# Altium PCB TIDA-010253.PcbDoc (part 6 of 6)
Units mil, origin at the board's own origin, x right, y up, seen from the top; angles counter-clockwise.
Board outline 5525 x 6695 mil, 4 copper layers (Top Layer, Signal Layer 1, Signal Layer 2, Bottom Layer), stack 61.2 mil thick; 522 components, 391 nets, 1722 pads, 1048 vias.
Unrouted connection lines stored in the file: 22.
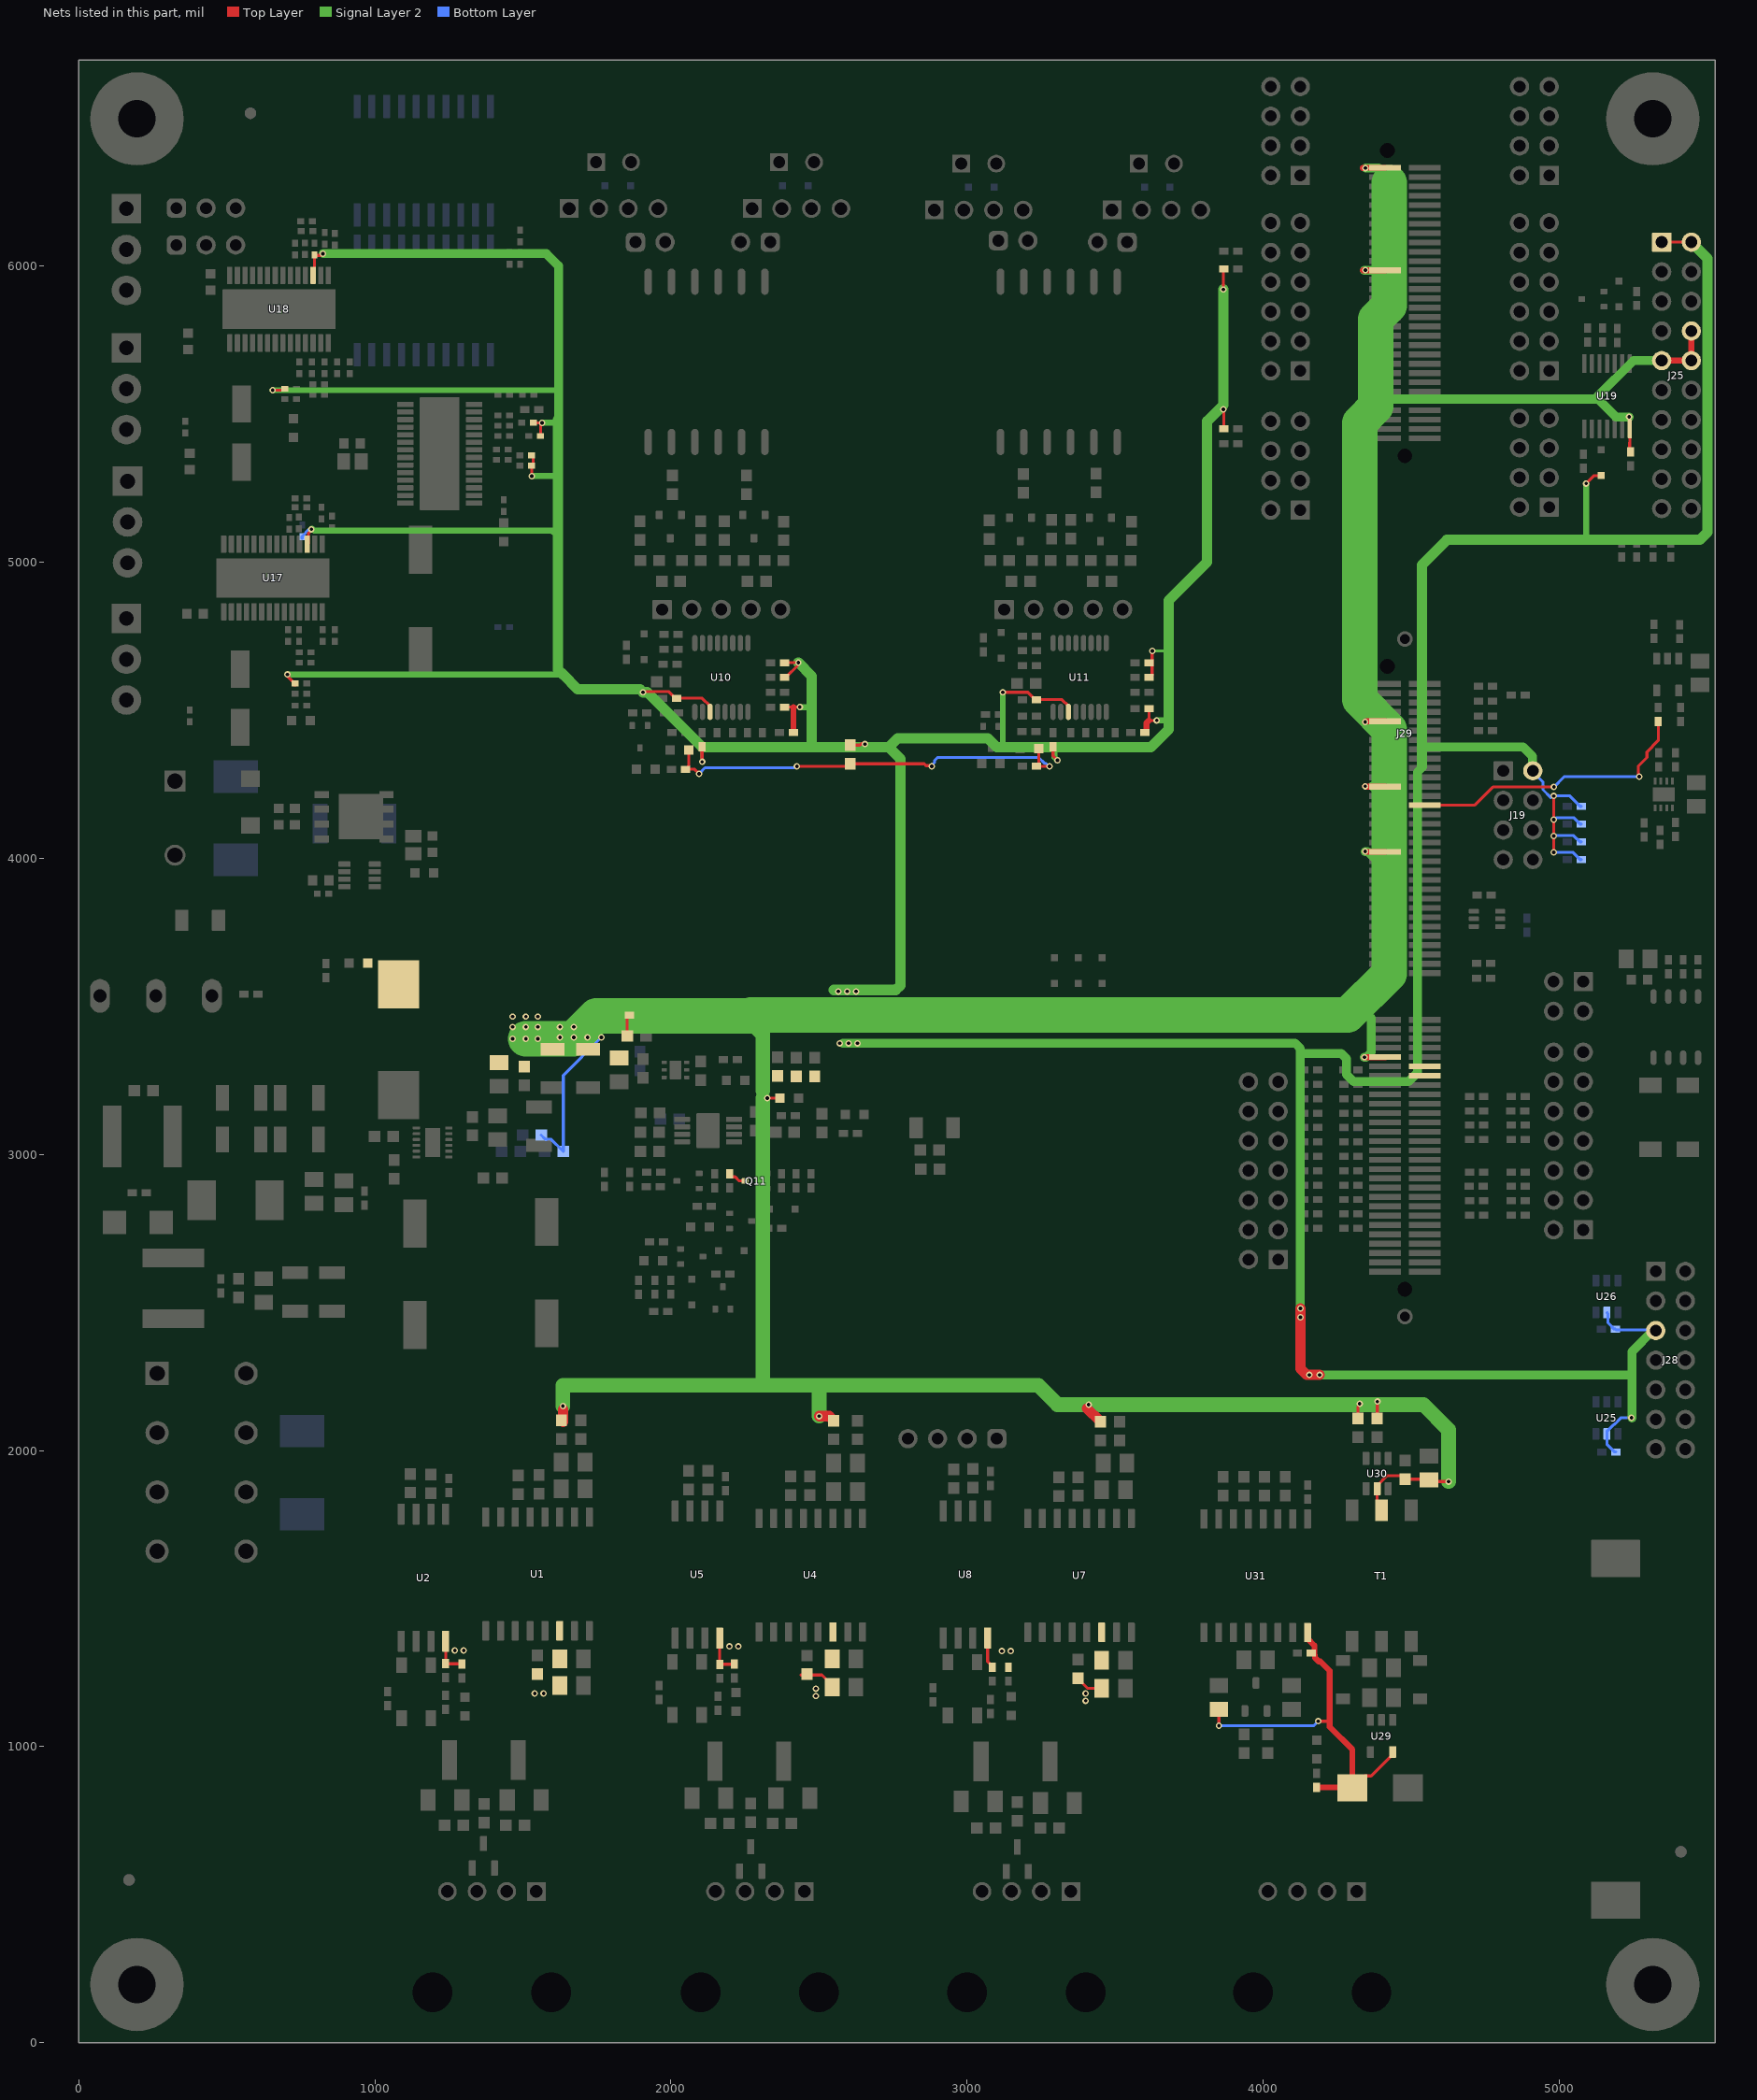
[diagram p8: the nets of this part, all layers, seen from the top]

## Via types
v1: diameter 22, hole 12, Top Layer to Bottom Layer, 944 vias
v2: diameter 19.68, hole 7.87, Top Layer to Bottom Layer, 76 vias
v3: diameter 19.68, hole 7.87, Top Layer to Bottom Layer, tented both sides, 16 vias
v4: diameter 22, hole 12, Top Layer to Bottom Layer, tented both sides, 12 vias

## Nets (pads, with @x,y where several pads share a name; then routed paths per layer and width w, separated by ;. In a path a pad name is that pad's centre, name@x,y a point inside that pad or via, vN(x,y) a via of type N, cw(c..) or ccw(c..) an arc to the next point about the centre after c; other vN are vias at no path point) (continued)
VCC5V: C49.1 C75.1 C113.1 C141.1 CO6.2 CO7.2 CO8.1 CO9.1 CO10.1 D35.2 D38.2 J25.8 J25.9 J25.10 J29.48 J29.84 J29.98 J29.112 J29.158 J29.180 L5.2 R5.1 R17.1 R30.1 R127.1 R133.2 R149.1 R208.1 R212.1 T1.2 U19.14 U30.2 | length 13922.4
  Top Layer w10: R127.1@1852,3400 1852,3463.19 1858.81,3470 R149.1@1859.99,3470 ; v1(2324.99,3190) D35.2@2367,3190 ; R212.1@4319.17,2107.36 4319.17,2148.22 ; R208.1@4384.17,2107.36 4385,2108.19 v1@4385,2155 ; T1.2@4399.17,1798.15 4384.17,1813.15 U30.2@4384.17,1870.87 4384.17,1880.71 4418.46,1915 4467.04,1915 C113.1@4479.17,1902.87 4557.16,1902.87 C141.1@4559.17,1900.87 4565.03,1895 v1(4625,1895) ; C75.1@5236.81,5380.43 5236.81,5402.48 5237.36,5403.03 U19.14@5237.36,5449.53
  Top Layer w20: v1@4335,6330 4335.54,6330 4336.37,6330.83 J29.180@4411.14,6330.83 ; v1@4335.54,5985 4336.17,5984.37 J29.158@4411.14,5984.37 ; v1(4341,3327.68) 4341.32,3327.99 4410.98,3327.99 J29.48@4411.14,3328.15 ; v1(4343.84,4022.68) 4344.38,4022.68 4346,4021.06 J29.84@4411.14,4021.06 ; v1(4343.84,4242.68) 4344.38,4242.68 4345.53,4241.54 J29.98@4411.14,4241.54 ; v1(4343.84,4460) 4344.38,4460 4346.39,4462.01 J29.112@4411.14,4462.01 ; J25.9@5345,5680 J25.10@5445,5680 J25.8@5445,5780
  Top Layer w35: R5.1@1635.83,2095.66 1635.83,2138.5 ; v1(2500,2115.87) 2534.17,2115.87 2546.98,2103.05 2547.97,2103.05 2549.17,2101.85 R17.1@2549.17,2100.87 ; 3405,2141.5 3447.81,2098.68 3448.8,2098.68 3450,2097.48 R30.1@3450,2096.5
  Signal Layer 2 w10: 2269.99,3445 2269.99,3460 ; 2310,3214.99 2324.99,3200 v1(2324.99,3190)
  Signal Layer 2 w30: v1@4340,5985 4385,5985 ; v1(4341,3327.68) 4347.43,3327.68 4365,3345.25 4365,3460 ; v1(4343.84,4022.68) 4352.32,4022.68 4375,4000 ; v1(4343.84,4460) 4375,4460 ; v1(4345,6330) 4390,6330 4420,6300 ; 4367.32,4242.68 4408.51,4201.49 ; 4380,5550 5130,5550 5190,5490 v1(5235,5490) ; 5127.5,5557.5 5250,5680 J25.9@5345,5680
  Signal Layer 2 w35: v1@4322.7,2155 v1(4325.16,2157.46) v1@4327.62,2155
  Signal Layer 2 w50: v1(1635,2150) 1635,2220 2310,2220 ; 2269.99,3445 2310,3404.99 2310,3214.99 ; 2310,3190 2310,2220 ; v1(2500,2115.87) 2500,2210 ; v1@4322.7,2155 v1(3410,2155) 3305,2155 3240,2220 2310,2220 ; v1@4327.62,2155 4385,2155 4540,2155 4625,2070 v1(4625,1895)
  Signal Layer 2 w120: v1(1509.99,3390) 1554.99,3390 1670,3390 1747.5,3467.5 2269.99,3467.5 ; 2269.99,3470 4285,3470 4425,3610 4425,4435 4325,4535 4325,5470 4380,5525 4380,5550 4380,5820 4425,5865 4425,6280
  Bottom Layer w10: C49.1@1561.48,3065 1575.19,3051.3 1594.2,3051.3 1635.5,3010 R133.2@1636.48,3010 1636.48,3266.5 v1(1764.99,3395)
  other v1: 4385,2165 1464.99,3390 1549.99,3390 1624.99,3395 1671.66,3395 1718.32,3395 1464.99,3430 1509.99,3430 1549.99,3430 1624.99,3430 1671.66,3430 1464.99,3465 1509.99,3465 1549.99,3465 4345,5985
VCC5V_485: C114.1 C139.2 R207.1 R216.1 U29.5 U31.16 | length 1347.1
  Top Layer w10: v1(3850,1070.87) R216.1@3850,1125.87 ; R216.1@3850,1135.87 R216.1@3856.5,1135.87 ; C139.2@4162.24,1315.87 C139.2@4166.18,1315.87 ; R207.1@4180,858.31 R207.1@4180,862.24 ; v1(4185,1085.87) 4223.6,1085.87 ; C114.1@4300.66,870.87 C114.1@4300.66,860.87 4340.94,901.14 4363.85,901.14 4436.57,973.86 U29.5@4436.57,981.73
  Top Layer w20: U31.16@4149.17,1384.96 4149.17,1364.29 4172.36,1341.1 4172.36,1310.24 C139.2@4174.17,1308.43 ; C139.2@4174.17,1304.49 4174.17,1300.55 4186.73,1287.99 4192.19,1287.99 4223.6,1256.59 4223.6,1085.87 4223.6,1067.27 4300.66,990.2 C114.1@4300.66,870.87 ; R207.1@4180,862.24 4299.29,862.24 C114.1@4300.66,860.87
  Bottom Layer w10: v1(3850,1070.87) 4170,1070.87 v1(4185,1085.87)
VCC5V_CAN0: C2.2 C4.1 CO2.1 R2.1 R7.2 U1.14 U2.8 | length 131.6
  Top Layer w10: U2.8@1239.17,1356.02 C2.2@1239.17,1280 1292.79,1280 R2.1@1294.17,1278.62
  other v1: 1540,1180 1570,1180 1270,1325 1300,1325
VCC5V_CAN1: C9.2 C11.1 CO4.1 R16.1 R20.2 U4.14 U5.8 | length 265.2
  Top Layer w10: U5.8@2164.17,1366.89 C9.2@2164.17,1278.11 2212.79,1278.11 R16.1@2214.17,1279.49 ; 2439.17,1241.89 2509.64,1241.89 2544.17,1207.37 C11.1@2544.17,1200.87
  other v1: 2489.17,1170.87 2489.17,1195.87 2197.3,1338.29 2227.3,1338.29
VCC5V_CAN2: C16.2 C18.1 CO11.1 R29.1 R33.2 U7.14 U8.8 | length 198.1
  Top Layer w10: U8.8@3069.17,1366.02 3069.17,1287.56 3084.17,1272.56 C16.2@3084.17,1268.62 ; R33.2@3374.17,1230.55 3374.17,1229.57 3406.69,1197.05 C18.1@3454.17,1197.05
  other v1: 3400,1155 3400,1180 3117.3,1322.42 3147.3,1322.42
VDDIO: C25.1 C36.1 C64.1 C65.1 C128.1 C129.1 D24.1 J19.2 J25.1 J25.2 J28.5 R41.2 R42.2 R47.1 R48.1 R49.1 R58.2 R59.2 R64.1 R65.1 R66.1 R71.1 R76.2 R77.2 R78.2 R79.2 R98.2 R100.2 R129.1 R130.1 R131.1 R159.2 R160.2 R199.2 R200.2 R222.2 R223.2 U10.3 U11.3 U17.3 U18.3 U25.5 U26.5 | length 22493.6
  Top Layer w10: v1(655,5580) 681,5580 681.16,5580.16 690.79,5580.16 R100.2@695.63,5585 ; v1@705.38,4613.28 R98.2@728.66,4590 ; U17.3@771.18,5056.5 775.27,5060.58 775.27,5096.72 787.65,5109.1 v1@787.65,5112.35 ; U18.3@791.18,5966.5 791.18,5987.17 796.02,5992.01 C65.1@796.02,6037.32 ; C65.1@805,6035 815.75,6035 821.75,6041 v4(825,6041) ; R76.2@1529.69,5325 1529.84,5324.84 1529.84,5290.16 v1(1530,5290) ; R76.2@1534.69,5325 R77.2@1534.69,5360 ; R79.2@1535,5470 v1(1565,5470) ; R78.2@1559.69,5425 v1@1559.69,5461.44 ; v1@1911.81,4561.81 1992.87,4561.81 2014.68,4540 C25.1@2018.62,4540 2105.25,4540 2131.61,4513.64 U10.3@2131.61,4493.86 ; v1@2105,4335 R42.2@2105,4376.38 ; R49.1@2383.62,4510 2413.62,4510 v1(2435,4510) ; R48.1@2383.62,4610 2387.56,4610 2427.7,4650.14 2427.7,4657.7 v1(2430,4660) R47.1@2383.62,4660 ; R71.1@2605,4381.5 2637.92,4381.5 2642.67,4386.24 v1@2645.92,4386.24 ; v1@3118.3,4560 v1(3120,4560) 3204.68,4560 3229.68,4535 C36.1@3233.62,4535 3320.25,4535 3341.61,4513.64 U11.3@3341.61,4493.86 ; R59.2@3290,4376.38 3290,4345.63 3305,4330.63 v1(3305,4330) ; R66.1@3613.62,4505 3613.62,4464.33 3639.33,4464.33 v1(3640,4465) ; R65.1@3613.62,4610 3617.56,4610 3624.37,4616.81 3624.37,4699.37 v1(3625,4700) ; v4(3865,5920) 3865,5988.62 R199.2@3866.38,5990 ; R200.2@3866.38,5450 v4@3866.38,5515 ; v1(4980,4020) v1(4980,4075) v1(4980,4130) v1(4980,4210) ; v1(5090,5265) 5116.69,5291.69 D24.1@5140,5291.69 ; J28.5@5310.61,2405 J28.5@5325,2405 ; J25.1@5345,6080 J25.2@5445,6080
  Top Layer w20: v1(705,4620) v1@705.38,4619.62 ; R98.2@728.66,4590 R98.2@730.31,4590 ; R41.2@2413.62,4425 2413.62,4510 ; R58.2@3600,4425 3603.94,4425 3605.75,4426.81 3605.75,4456.46 3613.62,4464.33
  Top Layer w35: v1(4125,2480) v1(4125,2450) 4125,2275.5 4145.5,2255 v1(4190,2255)
  Signal Layer 2 w10: v1@2105,4335 2105,4375 ; v1(3625,4700) 3680,4700
  Signal Layer 2 w20: v1(655,5580) 1610,5580 ; v1(705,4620) 1618.53,4620 1635,4620 ; v1@787.65,5112.35 788.19,5112.35 795.17,5105.37 1598.35,5105.37 1603.31,5100.41 ; v1@1535,5290 1615,5290 ; v1(1565,5470) 1615,5470 ; v1(2435,4510) 2465,4510 ; 3120,4380 v1(3120,4560) ; 3290,4365 3295,4360 3295,4340.54 3305,4330.54 v1(3305,4330) ; v1(3640,4465) 3680,4465 ; 5090,5090 v1(5090,5265)
  Signal Layer 2 w30: v4(825,6041) 1579,6041 1620,6000 1620,5470 ; v1@2579.63,3375 v1(2599.99,3375) v1(2629.99,3375) 4107.43,3375 4125,3357.43 4125,3340 ; v1(4125,2450) v1(4125,2480) 4125,3340 ; v1@4160,2255 v1(4190,2255) 5235,2255 5245,2245 ; 4535,4376 4876.43,4376 4908.31,4344.12 4908.31,4301.69 J19.2@4915,4295 ; 4537.5,4307.5 4520,4290 4520,3275 4490,3245 4305,3245 4281.26,3268.74 4281.26,3322.43 4263.69,3340 4125,3340 ; v1@5245,2110 5245,2245 ; J28.5@5325,2405 5315.54,2405 5245,2334.46 5245,2245
  Signal Layer 2 w35: 1618.53,5480 1618.53,4636.47 1635,4620 1685,4570 1895,4570 v1(1905,4560) 1920,4560 2105,4375 2705,4375 2735,4375 ; v1(2430,4660) 2475,4615 2475,4385 ; 2550,3555 2759.5,3555 2775,3570.5 2775,4335 2735,4375 ; v4(3865,5920) 3865,5530 3810,5475 3810,5000 3680,4870 3680,4700 3680,4465 3680,4435 3620,4375 3295,4375 3120,4375 3100,4375 3070,4405 2765,4405 2735,4375 ; 4535,4310 4535,4376 4535,4990 4620,5075 5474.5,5075 5499.98,5100.48 5499.98,6025.02 J25.2@5445,6080
  Bottom Layer w10: C64.1@754.17,5079.49 754.17,5086.14 778.08,5110.05 785.35,5110.05 v1@787.65,5112.35 ; J19.2@4915,4295 4915,4285.85 4944,4256.85 4944,4231.13 4970,4205.13 ; v1(4980,4020) 5044.69,4020 5069.69,3995 R159.2@5073.62,3995 ; v1(4980,4075) 4981.81,4076.81 5046.27,4076.81 5058.08,4065 5059.69,4065 5069.69,4055 R160.2@5073.62,4055 ; v1(4980,4130) 4983.25,4130 4990.06,4136.81 5047.87,4136.81 5069.69,4115 R222.2@5073.62,4115 ; v1(4980,4210) 5034.69,4210 5069.69,4175 R223.2@5073.62,4175 ; U26.5@5160,2465.87 5163.5,2462.36 5163.5,2431.18 5184.68,2410 C129.1@5188.62,2410 5191.12,2407.5 5322.5,2407.5 J28.5@5325,2405 ; C128.1@5190,1995 5186.06,1995 5160,2021.06 U25.5@5160,2055.87 5160,2063.74 5206.26,2110 v1@5240,2110
  other v1: 5243,2110 4155,2255 2570,3375 2565,3550 2594.99,3550 2624.99,3550 2105,4325 2655,4385 785.65,5110.35
  other v4: 3865,5515
VDDIO_LED: D11.2 D16.2 R52.2 R69.2 R71.2 | length 1443.4
  Top Layer w10: R52.2@2048.62,4300 2080,4300 v1(2095,4285) ; R52.2@2053.19,4305 2060,4311.81 D11.2@2060,4365 ; v1(2425,4310) 2596.5,4310 R71.2@2605,4318.5 2855,4318.5 2861.21,4312.3 2877.7,4312.3 v1(2880,4310) ; R69.2@3233.62,4310 R69.2@3234.69,4310 ; D16.2@3241.5,4370 3241.5,4316.81 R69.2@3234.69,4310 ; v1(3278,4310) R69.2@3234.69,4310
  Bottom Layer w10: v1(2095,4285) 2115,4305 v1@2416.75,4305 ; v1(2880,4310) 2880,4313.25 2890,4323.25 2890,4330 2900,4340 3241.75,4340 3261.97,4319.79 3264.97,4319.79 3274.75,4310 v1(3278,4310)
VREFHI: J29.45
VREFLO: J29.43
WAKE_C: Q11.3 R143.1 | length 64.2
  Top Layer w10: R143.1@2197.59,2933.62 2197.59,2930.44 2204.4,2923.63 2216.37,2923.63 2229.52,2910.48 2249.71,2910.48 Q11.3@2250.19,2910
WTD_WI: J29.93 R154.2 | length 974.9
  Top Layer w10: J29.93@4545,4178.54 4545.73,4179.27 4714.27,4179.27 4775,4240 v1@4980,4240 ; v1@5266,4275 5266,4311 5295,4340 5295,4358.5 5333.62,4397.13 R154.2@5333.62,4461.38
  Bottom Layer w10: v1(4981,4240) 5015,4274 5015,4275 v1@5266,4275
  other v1: 5269,4275
pads on no net: FID1.1 FID2.1 FID3.1 FID4.1 FID5.1 FID6.1 H1.1 H2.1 H3.1 H4.1 J1.1 J1.MH1 J1.MH2 J2.1 J2.MH1 J2.MH2 J4.1 J4.2 J8.3 J8.4 J9.1 J9.2 J13.3 J13.4 J20.1 J20.3 J25.4 J25.6 J25.12 J25.14 J25.16 J28.6 J29.41 J29.44 J29.56 J29.66 J29.68 J29.70 J29.113 J29.114 J29.115 J29.116 J29.117 J29.118 J29.119 J29.136 J29.171 J29.172 J29.173 J29.174 J29.175 J29.176 J29.177 J29.178 J29.181 J29.182 J29.183 J29.184 J29.185 J29.186 J30.1 J30.MH1 J30.MH2 J31.1 J31.MH1 J31.MH2 LBL1.0 T2.8 T2.11 T3.8 T3.11 U13.2 U13.19 U13.24 U13.29@1218.86,5365.43 U14.4 U14.7 U15.10 U15.11 U16.10 U16.11 U19.3 U19.11 U22.5 U22.7@2014.99,3267.28 U22.7@2014.99,3302.72 U23.6 U23.9@2124.99,3080 U29.4 U31.7 U31.10 U31.11 U31.14 Y1.2 Y1.3

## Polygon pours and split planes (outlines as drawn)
GND on Signal Layer 1 "GND_L02_P051" (solid, remove dead copper, pour order 51): 25,6715 25,0 5530,0 5530,6695 5520,6705
PGND on Signal Layer 1 "PGND_L02_P049" (solid, remove dead copper, pour order 49): 0,6695 2020,6695 2030,6705 2935,6705 2935,5 2930,0 0,0
GND2 on Signal Layer 1 "GND2_L02_P066" (solid, remove dead copper, pour order 66): 3790,1385 4560,1385 4560,0 3790,0
GND4 on Signal Layer 1 "GND4_L02_P060" (solid, remove dead copper, pour order 60): 2865,1385 3578.5,1385 3578.5,7.48 2865,7.48
GND1 on Signal Layer 1 "GND1_L02_P057" (solid, remove dead copper, pour order 57): 1940,1380 2653.99,1380 2653.99,0 1940,0
GND0 on Signal Layer 1 "GND0_L02_P054" (solid, remove dead copper, pour order 54): 1018.15,1385 1750,1385 1750,0 1028.15,0 1028.15,500 1018.15,500
GND on Bottom Layer "GND_L04_P069" (solid, remove dead copper, pour order 69): 25,6715 25,0 5530,0 5530,6695 5520,6705
PGND on Bottom Layer "PGND_L04_P048" (solid, remove dead copper, pour order 48): 0,6695 2020,6695 2030,6705 2935,6705 2935,5 2930,0 0,0
GND0 on Bottom Layer "GND0_L04_P056" (solid, remove dead copper, pour order 56): 1018.15,1385 1750,1385 1750,0 1028.15,0 1028.15,500 1018.15,500
GND1 on Bottom Layer "GND1_L04_P059" (solid, remove dead copper, pour order 59): 1940,1380 2653.99,1380 2653.99,0 1940,0
GND2 on Bottom Layer "GND2_L04_P068" (solid, remove dead copper, pour order 68): 3790,1385 4560,1385 4560,0 3790,0
GND4 on Bottom Layer "GND4_L04_P062" (solid, remove dead copper, pour order 62): 2865,1385 3578.5,1385 3578.5,7.48 2865,7.48
GND on Top Layer "GND_L01_P065" (solid, remove dead copper, pour order 65): 25,6715 25,0 5530,0 5530,6695 5520,6705
PGND on Top Layer "PGND_L01_P021" (solid, remove dead copper, pour order 21): 0,6695 2020,6695 2030,6705 2935,6705 2935,5 2930,0 0,0
GND1 on Top Layer "GND1_L01_P023" (solid, remove dead copper, pour order 23): 1940,1380 2653.99,1380 2653.99,0 1940,0
GND0 on Top Layer "GND0_L01_P022" (solid, remove dead copper, pour order 22): 1018.15,1385 1750,1385 1750,0 1028.15,0 1028.15,500 1018.15,500
GND2 on Top Layer "GND2_L01_P064" (solid, remove dead copper, pour order 64): 3790,1385 4560,1385 4560,0 3790,0
GND4 on Top Layer "GND4_L01_P038" (solid, remove dead copper, pour order 38): 2865,1385 3578.5,1385 3578.5,7.48 2865,7.48
GND on Signal Layer 2 "GND_L03_P052" (solid, remove dead copper, pour order 52): 25,6715 25,0 5530,0 5530,6695 5520,6705
PGND on Signal Layer 2 "PGND_L03_P045" (solid, remove dead copper, pour order 45): 0,6695 2020,6695 2030,6705 2935,6705 2935,5 2930,0 0,0
GND0 on Signal Layer 2 "GND0_L03_P053" (solid, remove dead copper, pour order 53): 1018.15,1385 1750,1385 1750,0 1028.15,0 1028.15,500 1018.15,500
GND2 on Signal Layer 2 "GND2_L03_P067" (solid, remove dead copper, pour order 67): 3790,1385 4560,1385 4560,0 3790,0
GND4 on Signal Layer 2 "GND4_L03_P061" (solid, remove dead copper, pour order 61): 2865,1385 3578.5,1385 3578.5,7.48 2865,7.48
GND1 on Signal Layer 2 "GND1_L03_P055" (solid, remove dead copper, pour order 55): 1940,1380 2653.99,1380 2653.99,0 1940,0

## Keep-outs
Keep-Out Layer:
  text ".Layer_Name" at 577,-858.49 h60

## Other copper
Top Layer:
  region net HS_OUT2: 1010,5305 1010,5225 1065,5225 1065,5240 1135,5240 1135,5280 1070,5280 1070,5300 1065,5305
  region net LS_OUT4: 580,5945 580,6110 640,6110 645,6105 645,5945
  region net LS_OUT3: 580,5765 580,5705 575,5700 605,5670 645,5710 645,5765
  region net HS_OUT4: 655,5770 725,5770 720,5765 720,5605 715,5600 655,5600
  region net HS_OUT4: 655,5940 655,6105 710,6105 715,6100 715,5940
  region net LS_OUT2: 560,5030 560,5090 430,5220 110,5220 110,5325 180,5325 185,5320 190,5325 440,5325 625,5140 625,5035
  region net HS_OUT1: 1075,5215 1075,5235 1130,5235 1130,5165 1130,5160 1120,5160 1010,5160 1010,5215
  region net HS_OUT1: 985,521 985,461 1137.5,461 1137.5,521
  region net VCC5V: 979.99,3480 1009.99,3450 1119.99,3450 1239.99,3330 1289.99,3280 1559.99,3280 1584.99,3295 1874.99,3295 1874.99,3480 1844.99,3480 1844.99,3425 1839.99,3420 1794.99,3420 1769.99,3445 1619.99,3445 1609.99,3455 1609.99,3490 1454.99,3645 979.99,3645
  region net PGND: 2084.99,3120 2086.6,3118.39 2249.63,3118.39 2259.55,3128.31 2262.86,3125 2324.99,3125 2324.99,3160 2279.99,3205 2204.99,3205 2204.99,3265 2199.99,3270 2034.99,3270 2034.99,3335 2059.99,3335 2064.99,3340 2064.99,3390 1969.99,3390 1969.99,3340 1979.99,3340 1994.99,3325 1994.99,3270 1881.49,3270 1881.49,3260 1412.49,3260 1404.99,3260 1369.99,3225 1164.99,3225 1164.99,2980 1139.99,2955 1029.99,2955 904.99,3080 904.99,3185 904.99,3455 857.85,3455 310,3455 245,3390 245,2955 504.99,2955 504.99,3260 760,3260 760,2865 1394.99,2865 1394.99,2985 1279.99,2985 1279.99,2970 1244.99,2970 1224.99,2990 1224.99,3106.5 1328.49,3106.5 1328.49,3110 1914.99,3110 1914.99,3185 2084.99,3185
  region net GND: 3509.17,1982.05 3509.17,1822.05 3489.17,1802.05 3489.17,1737.05 3514.17,1737.05 3519.17,1742.05 3519.17,1792.05 3605,1877.88 3605,1982.05
  region net NetC17_1: 3439.17,1732.05 3459.17,1732.05 3469.17,1742.05 3469.17,1807.05 3489.17,1827.05 3489.17,1982.05 3519.17,2012.05 3534.17,2012.05 3534.17,2047.05 3539.17,2052.05 3429.17,2052.05 3429.17,1742.05
  region net GND: 3194.17,1737.05 3314.17,1737.05 3314.17,1792.05 3279.17,1827.05 3279.17,1882.05 3279.17,1887.05 3404.17,1887.05 3414.17,1897.05 3414.17,1972.05 3219.17,1972.05 3194.17,1947.05
  region net VCC5V_CAN2: 3070,1385 3070,1260 3075,1255 3165,1255 3165,1385
  region net GND4: 3539.9,1354.27 3504.9,1319.27 3499.9,1319.27 3499.9,1169.27 3509.9,1159.27 3569.9,1159.27 3569.9,1351.32 3566.94,1354.27
  region net VCC5V_CAN2: 3350,1260 3350,1160 3370,1140 3475,1140 3480,1145 3479.17,1145.83 3479.17,1250.83 3470,1260
  region net GND4: 3186.67,1422.05 3306.67,1422.05 3311.67,1417.05 3361.67,1417.05 3361.67,1357.05 3331.67,1327.05 3331.67,1157.05 3356.67,1132.05 3486.67,1132.05 3486.67,1162.05 3505.42,1180.8 3524.17,1162.05 3566.67,1162.05 3566.67,1070.91 3547.8,1052.05 3181.67,1052.05
  region net VCC5V_CAN2: 3439.9,1354.27 3424.9,1339.27 3424.9,1159.27 3474.9,1159.27 3474.9,1164.27 3474.9,1344.27 3464.9,1354.27
  region net GND4: 3127.13,1126.38 3120,1119.25 3120,1045 3200,1045 3240,1085 3240,1125
  region net NetC10_1: 2534.17,1735.87 2554.17,1735.87 2564.17,1745.87 2564.17,1810.87 2584.17,1830.87 2584.17,1985.87 2614.17,2015.87 2629.17,2015.87 2629.17,2050.87 2634.17,2055.87 2524.17,2055.87 2524.17,1745.87
  region net VCC5V_CAN1: 2150,1400.87 2150,1275.87 2155,1270.87 2245,1270.87 2245,1400.87
  region net GND: 2289.17,1740.87 2409.17,1740.87 2409.17,1795.87 2374.17,1830.87 2374.17,1885.87 2374.17,1890.87 2499.17,1890.87 2509.17,1900.87 2509.17,1975.87 2314.17,1975.87 2289.17,1950.87
  region net GND1: 2207.13,1132.24 2200,1125.12 2200,1050.87 2280,1050.87 2320,1090.87 2320,1130.87
  region net VCC5V_CAN1: 2435,1275.87 2435,1175.87 2455,1155.87 2560,1155.87 2565,1160.87 2564.17,1161.7 2564.17,1266.7 2555,1275.87
  region net VCC5V_CAN1: 2534.9,1358.09 2519.9,1343.09 2519.9,1163.09 2569.9,1163.09 2569.9,1168.09 2569.9,1348.09 2559.9,1358.09
  region net GND: 2604.17,1985.87 2604.17,1825.87 2584.17,1805.87 2584.17,1740.87 2609.17,1740.87 2614.17,1745.87 2614.17,1795.87 2695,1876.7 2695,1985.87
  region net GND1: 2276.67,1055.87 2642.8,1055.87 2661.67,1074.73 2661.67,1163.09 2664.9,1163.09 2664.9,1348.09 2654.9,1358.09 2634.9,1358.09 2599.9,1323.09 2594.9,1323.09 2594.9,1163.99 2581.67,1155.55 2581.67,1135.87 2451.67,1135.87 2426.67,1160.87 2426.67,1330.87 2456.67,1360.87 2456.67,1420.87 2406.67,1420.87 2401.67,1425.87 2281.67,1425.87
  region net NetC3_1: 1605,1995 1605,2060 1715,2060 1710,2055 1710,2020 1695,2020 1665,1990
  region net NetC3_1: 1615,1745 1605,1755 1605,2000 1660,2000 1665,1995 1665,1840 1645,1820 1645,1755 1635,1745
  region net VCC5V_CAN0: 1520,1265 1520,1165 1540,1145 1645,1145 1650,1150 1649.17,1150.83 1649.17,1255.83 1640,1265
  region net VCC5V_CAN0: 1614.17,1360 1599.17,1345 1599.17,1165 1649.17,1165 1649.17,1170 1649.17,1350 1639.17,1360
  region net GND: 1679.17,1989.17 1679.17,1829.17 1659.17,1809.17 1659.17,1744.17 1684.17,1744.17 1689.17,1749.17 1689.17,1799.17 1770,1880 1770,1989.17
  region net GND: 1364.17,1745 1484.17,1745 1484.17,1800 1449.17,1835 1449.17,1890 1449.17,1895 1574.17,1895 1584.17,1905 1584.17,1980 1389.17,1980 1364.17,1955
  region net GND0: 1364.17,1425 1484.17,1425 1489.17,1420 1539.17,1420 1539.17,1360 1509.17,1330 1509.17,1160 1534.17,1135 1664.17,1135 1664.17,1165 1674.17,1175 1684.17,1165 1744.17,1165 1744.17,1073.86 1725.3,1055 1359.17,1055
  region net GND0: 1714.17,1360 1679.17,1325 1674.17,1325 1674.17,1175 1684.17,1165 1744.17,1165 1744.17,1350 1734.17,1360
  region net VBATF: 1566.16,2695 1629.99,2690 1629.99,2955 1629.99,2990 1884.99,2990 1884.99,3020 1859.99,3045 1604.99,3045 1554.99,3095 1274.99,3095 1234.99,3095 1234.99,3050 1239.99,3045 1279.99,3045 1304.99,3020 1469.99,3020 1469.99,2845 730,2845 705.43,2869.57 705.43,3094.57 704.99,3165 704.99,3240 545,3240 545,2770 620,2695
  region net VBATP: 215.01,2570 900,2570 900,2680 585,2680 495,2770 495,2945 220,2945 215.01,2934.99
  region net PGND: 215,2020 570,2020 570,2115 570,2365 455,2480 215,2480
  region net VBATI: 575,1615 0,1615 0,3390 200,3390 200,1970 575,1970
  region net VCC3V3: 2194.99,3395 2289.99,3395 2289.99,3340 2194.99,3340
  region net VCC3V3: 2279.99,3310 2284.99,3305 2509.99,3305 2509.99,3350 2509.99,3395 2279.99,3395
  region net BQ_12V: 2184.99,3050 2244.99,3050 2249.99,3045 2394.99,3045 2404.99,3055 2404.99,3095 2509.99,3095 2514.99,3090 2514.99,3000 2214.99,3000 2184.99,3030
  region net VCC3V3: 2154.99,3305 2149.99,3310 2149.99,3395 2194.99,3395 2194.99,3305
  region net VDDIO: 2334.99,3290 2334.99,3240 2359.99,3215 2584.99,3215 2599.99,3230 2599.99,3295 2339.99,3295
  region net VDDIO: 2534.99,3295 2534.99,3570 2659.99,3570 2659.99,3215 2539.99,3215
  region net PGND: 1279.99,2985 1259.99,2970 1279.99,2970
  region net NetCBoot1_1: 1028.99,3280 1040,3248.54 1040,3045 1129.99,3045 1149.99,3045 1149.99,3280
  region net PGND: 2084.99,3035 2084.99,3025 2069.99,3010 2069.99,3000 2179.99,3000 2179.99,3010 2164.99,3025 2164.99,3035
  region net PGND: 389.99,2445 484.99,2350 1769.99,2350 1769.99,2465.95 1769.99,2545 954.99,2545 220,2545 220,2445
  region net VCC5V_CAN0: 1225,1390 1225,1265 1230,1260 1320,1260 1320,1390
  region net GND0: 1297.13,1121.38 1290,1114.25 1290,1040 1370,1040 1410,1080 1410,1120
  region net 24V: 1055,4065 1072.5,4082.5 1325,4082.5 1325,4682.5 1385,4742.5 1385,5120 1190,5120 1190,4990 1265,4915 1265,4747.5 1225,4707.5 1225,4267.5 1200,4242.5 875,4242.5 875,4082.5 892.5,4065
  region net PGND: 1365,5635 1565,5635 1585,5615 1585,5605 1395,5605 1375,5585
  region net PGND: 1160,5175 1160,5150 1155,5145 1010,5145 1010,5130 1395,5130 1395,5155 1375,5175
  region net PGND: 1155,5525 1155,5565 1065,5565 1050,5580 1050,5605 1080,5635 1365,5635 1375,5625 1375,5585 1360,5570 1305,5570 1290,5555 1290,5525
  region net PGND: 470,5110 465,5105 465,4795 545,4795 550,4800 550,5085 545,5085 515,5115 465,5115
  region net PGND: 405,4860 405,4810 415,4800 550,4800 550,4860 545,4865 410,4865
  region net PGND: 467.09,5019.49 539.49,5019.49 550,5030 550,5085 545,5085 515,5115 465,5115
  region net 24V_CONN: 610,4055 775,4055 785,4065 785,4095 610,4095
  region net 24V_CONN: 610,4080 645,4080 660,4095 850,4095 850,4120 855,4130 855,4135 855,4230 785,4230 780,4230 770,4225 770,4140 495,4140 450,4095 450,3715 610,3715 610,3880
  region net PGND: 500,5995 570,5995 570,5715 565,5710 500,5710
  region net PGND: 280,4470 650,4470 650,4390 685,4390 700,4405 830,4405 850,4385 850,4270 780,4270 750,4240 750,4155 645,4155 625,4175 280,4175
  region net PGND: 1015,4770 1015,4560 1185,4560 1210,4585 1210,4770
  region net GND: 5285,4285 5285,4205 5300,4190 5410,4190 5425,4175 5425,4060 5495,4060 5495,4200 5445,4200 5405,4240 5335,4240 5330,4240 5330,4270 5310,4290 5305,4305 5285,4305
  region net GND2: 4390,1015.87 4450,1015.87 4460,1005.87 4460,915.87 4445,900.87 4445,820.87 4550,820.87 4550,1050.87 4425,1050.87 4410,1065.87 4410,1098.37 4392.5,1098.37 4390,1095.87
  region net GND2: 4380,1395.87 4335,1350.87 4335,1265.87 4325,1255.87 4270,1245.87 4270,1197.79 4335,1182.79 4335,1135.87 4370,1135.87 4390,1115.87 4390,1075.87 4405,1075.87 4410,1070.87 4410,1125.87 4395,1140.87 4399.17,1145.03 4399.17,1395.03 4400,1395.87
  region net PGND: 265,5420 265,5340 470,5340 535,5275 905,5275 920,5290 920,5445 270,5445
  region net HS_OUT4: 1135,5545 1135,5495 1065,5495 985,5495 985,5545
  region net HS_OUT1: 680,4780 680,4635 655,4610 555,4610 540,4700 570,4725 640,4780
  region net LS_OUT1: 625,4855 560,4855 560,4795 530,4765 530,4714.47 625,4784.47
  region net HS_OUT1: 705,4855 705,4800 695,4800 680,4785 680,4780 660,4780 650,4780 635,4770 635,4800 635,4855
  region net HS_OUT1: 635,5195 635,5035 690.19,5035 700,5085 690,5095 690,5195
  region net LS_OUT1: 531.54,4715 220,4715 175,4760 110,4760 110,4860 329.88,4860 399.88,4790 560.38,4790
  region net HS_OUT1: 535,4580 445,4490 120,4490 120,4545 135,4560 140,4555 420,4555 515,4650 515,4686.5 523.5,4695
  region net 24V: 930,5320 930,4955 1070,4955 1005,5074.74 1005,5320
  region net 24V: 975.29,5120 1200,5120 1210,5110 1210,4955 980,4955
  region net NetF1_1: 195,4045 80,3930 80,3715 375,3715 375,4005 375,4045
  region net HS_OUT3: 1135,5485 1135,5445 1065,5445 1065,5435 975,5435 975,5485
  region net 24V: 1132.68,5316.02 1067.68,5316.02 935,5316.02 935,5426.02 1062.68,5426.02 1082.68,5406.02 1132.68,5406.02
  text ".Layer_Name" at 577,-858.49 h60
Signal Layer 2:
  region net VCC5V: 1449.99,3475 1459.99,3485 1599.99,3485 1639.99,3445 1779.99,3445 1779.99,3345 1764.99,3330 1484.99,3330 1449.99,3365
Bottom Layer:
  region net 24V_CONN: 665,4080 675,4090 675,4120 810,4120 810,4055 665,4055
  region net VCC5V_CAN2: 3085,1385 3080,1380 3080,1150 3440,1150 3450,1150 3450,1180 3450,1240 3200,1240 3170,1270 3170,1385
  region net VCC5V_CAN1: 2165,1400.87 2160,1395.87 2160,1165.87 2520,1165.87 2530,1165.87 2530,1195.87 2530,1255.87 2280,1255.87 2250,1285.87 2250,1400.87
  region net PGND: 217.91,2340.86 222.91,2345.86 835,2345.86 835,2010.86 207.91,2010.86
  region net VBATI: 225,1955 230,1960 830,1960 830,1625 215,1625
  region net VCC5V_CAN0: 1230,1390 1225,1385 1225,1155 1585,1155 1595,1155 1595,1185 1595,1245 1345,1245 1315,1275 1315,1390
  region net LS_OUT_COM: 965,6145 975,6145 1050,6070 1380,6070 1310,6140 1310,6205 1295,6220 935,6220 920,6205 920,6175
  region net 24V: 900,4210 900,4070 1065,4070 1070,4075 1070,4205 1065,4210
  region net PGND: 460,4330 665,4330 735,4400 825,4400 825,4310 825,4300 810,4275 740,4275 690,4225 460,4225
  region net 24V_CONN: 455,4050 455,3850 600,3850 605,3860 605,3875 605,4055
  region net LS_OUT_COM: 930,6190 910,6190 875,6225 875,6320 820,6320 820,6195 870,6145 965,6145
  region net HS_OUT4: 985,5550 1065,5550 1065,5495 975,5495 975,5550
  region net HS_OUT1: 635,5200 635,5105 645,5095 695,5095 695,5200
  text ".Layer_Name" at 577,-858.49 h60
Multi-Layer:
  pour cut-out: 745,1735.87 4400,1735.87 4400,1710 4450,1660 4455,1665 4852.75,1665 4870,1647.74 4870,1540 4845,1565 4845,1645 4400,1645 4375,1670 4375,1710 745,1710
  pour cut-out: 1485,3705 1505,3705 1505,3675 1600,3580 2830,3580 2885,3525 2885,2475 2735,2325 840,2325 840,1805 600,1565 0,1565 0,1600 4.19,1604.19 599.19,1604.19 805,1810 805,2355 2735,2355 2870,2490 2870,3520 2825,3565 1595,3565 1485,3675
  pour cut-out: 1330,4805 1330,4850 1510,5030 1510,5740 1510,6695 1495,6695 1495,5041.25 1315,4861.25 1315,4790
  pour cut-out: 3655.65,4905 3655.65,5920 3965.65,6230 3965.65,6697.28 1510.65,6697.28 1510.65,5950 1800.65,5660 1784.35,4905
  pour cut-out: 4830,1645 4830,0 4870,0 4870,1647.74
  pour cut-out: 1315,3875 1485,3705 1505,3705 1420,3790 1385,3825 1330,3880 1330,4805 1315,4790
  pour cut-out: 5295,3355 5395,3355 5395,3305 5465,3235 5480,3235 5480,2950 5475,2945 5390,2945 5390,2955 5475,2955 5475,3230 5460,3230 5385,3305 5385,3350 5300,3350 5295,3345
  pour cut-out: 5300,3350 5295,3355 5295,3300 5255,3260 5255,2945 5390,2945 5390,2955 5275,2955 5260,2970 5260,3255 5300,3295

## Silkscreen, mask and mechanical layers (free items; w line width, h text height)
Top Overlay:
  lines w10: 470,5225 670,5225 690,5205 ; 755,4640 820,4640 1005,4640 1020,4625 1020,4275 1005,4260 845,4260 835,4270 835,4640 ; 895,5570 915,5550 930,5550 945,5565 945,5570 ; 935,5785 935,5580 945,5570 ; 940,5775 1185,5775 1190,5770 1190,5580 1180,5570 945,5570 ; 1010,6510 1085,6510 ; 1010,6565 1095,6565 1105,6555 1105,6510 ; 1095,6500 1105,6510 ; 1130,6565 1210,6565 ; 1210,6510 1105,6510 ; 1714.99,3695 1714.99,3550 1754.99,3510 2444.99,3510 2464.99,3530 2464.99,3695 ; 1715,3700 1765,3750 2415,3750 2465,3700 ; 1724.99,3480 1749.99,3505 1784.99,3505 ; 1894.99,2475 1894.99,2420 1959.99,2355 ; 1960,2210 1980,2190 2305,2190 2305,2430 2294.99,2440 1964.99,2440 1959.99,2435 ; 1960,2210.87 1960,2435.87 ; 2395,5245 2430,5245 ; 2415,4915 3005,4915 3005,5100 ; 2415,5105 3005,5105 ; 2415,5290 2995,5290 ; 2430,5105 2430,5290 ; 2439.99,2790 2469.99,2760 2509.99,2760 ; 2529.99,2670 2519.99,2680 2519.99,2890 2539.99,2910 ; 2540,2670 3040,2670 3070,2700 3070,2910 2550,2910 ; 2715,5255 2715,5290 ; 2720,5070 2720,5105 ; 3010,4950 3045,4950 ; 5125,6025 5125,5970 5130,5965 ; 290,5070 290,5280 435,5280 465,5250 465,5095 440,5070 290,5070 ; 575,6215 575,6370 590,6385 795,6385 810,6370 810,6195 595,6195 575,6215 ; 1585,4285 1585,4800 1790,4800 1805,4785 1805,4270 1795,4280 1590,4280 1585,4285 ; 2780,4365 2780,4780 2800,4800 2985,4800 2985,4340 2805,4340 2780,4365 ; 2790,3275 2790,3525 3075,3525 3130,3470 3130,3275 2790,3275 ; 5060,6050 5060,6305 5090,6335 5230,6335 5240,6325 5240,6050 5220,6030 5080,6030 5060,6050
  text "LSD_4" at 1240,6545.83 h35
  text "GND" at 890,6535 h35
  text "LSD_C" at 825,6480.83 h35
  text "PCHG" at 1245,6480 h35
  text "UIR" at 5295,6225 h80
  text "X=4,3,2,1 / LSD_X / LSD_C / HSD_X" at 970,6070 h50
  text "BQ0" at 2460,5555 h80
  text "BQ1" at 2780,5555 h80
  text "H->L" at 2605,5455 h60
  text "PN NP" at 2585,5365 h60
  text "GND/VIO" at 5005,4280.02 h60
  text "DVDD" at 3005,4245 h30
  text "FLT" at 3165,4245 h30
  text "DVDD" at 1820,4225 h30
  text "FLT" at 1980,4225 h30
  text "IC_2/1_IO" at 5005,4149.99 h60
  text "IC2_D/CL" at 5005,4075 h30
  text "IC1_D/CL" at 5005,3980 h30
  text "24V" at 1224,3879 h25
  text "24V_2" at 75,3763.33 h50
  text "12V" at 2695,3615 h50
  text "5VPG" at 2799,3479 h25
  text "5V" at 2859,3444 h25
  text "3.3V" at 2315,3435 h50
  text "33V" at 2894,3409 h25
  text "5V" at 1320,3390 h50
  text "BQ0/BQ1/IG / wake" at 3160,3370 h50
  text "12PG" at 2934,3369 h25
  text "12V" at 3044,3344 h25
  text "BAT" at 2899,3329 h25
  text "OFF" at 360,3310 h50
  text "ON" at 50,3305 h50
  text "K15" at 2844,3289 h25
  text "VDDIO" at 2545,3235 h50
  text "MCU_WK" at 2515,2933.33 h50
  text "5V" at 1590,2240 h50
  text "DE" at 3920,2205 h50 r270
  text "RE" at 3990,2200 h50 r270
  text "TX" at 1165,2195 h50 r270
  text "RX" at 1085,2190 h50 r270
  text "PGND" at 680,2155 h50
  text "D" at 3845,2155 h50 r270
  text "R" at 4065,2150 h50 r270
  text "3.3V" at 1310,2100 h50 r270
  text "5V" at 4675,1860 h50
  text "Debug" at 5065,1816.66 h80
  text "24V_1" at 670,1773.33 h50
  text "L" at 1470,580 h50
  text "A" at 4100,580 h50
  text "B" at 4190,580 h50
  text "H" at 1235,570 h50
  text "CAN1" at 1895,135 h80 r90
  text "RS485" at 3720.15,131.06 h80 r90
  text "CAN0" at 950,115 h80 r90
  text "CAN2" at 2775.15,111.06 h80 r90
  text ".Layer_Name" at 577,-858.49 h60
Bottom Overlay:
  text "GND" at 4194,6594 h20
  text "GND" at 4299,6594 h20
  text "GND" at 4494,6464 h20
  text "GND" at 4663.33,6463.66 h20
  text "AMUR2_TX" at 4664,6427.33 h20
  text "AMUR0_TX" at 4193.53,6387.8 h20
  text "AMUR2_RX" at 4493.53,6387.8 h20
  text "AMUR0_RX" at 4658.53,6387.8 h20
  text "AMUR1_RX" at 4494,6352.33 h20
  text "ＶＤＤＩＯ" at 5099,6254 h20
  text "VDDIO" at 5204,6254 h20
  text "OC1" at 5097.96,6213.83 h20
  text "AMUR1_TX" at 3968.53,6212.8 h20
  text "STEAP1" at 4137.45,6210.15 h20
  text "GND" at 4839,6184 h20
  text "GND" at 4944,6184 h20
  text "OC2" at 5097.96,6173.83 h20
  text "nFLT" at 5097.96,6138.83 h20
  text "VCC5V" at 5204,6138.83 h20
  text "GND" at 4184,6129 h20
  text "GND" at 4289,6129 h20
  text "VCC5V" at 5097.96,6103.83 h20
  text "VCC5V" at 5204,6104 h20
  text "MOSI" at 5100.35,6068.78 h20
  text "MISO" at 5099,6034 h20
  text "CS" at 5099,5999 h20
  text "CLK" at 5099,5964 h20
  text "UIREN" at 5204,5964 h20
  text "GND" at 5099,5924 h20
  text "GND" at 5204,5924 h20
  text "GND" at 5018.77,5470.74 h20
  text "GND" at 3929,5464 h20
  text "STRAP2" at 3869,5374 h20
  text "LSD_FT1" at 4794,5092.33 h20
  text "FLT_ALL" at 4939,5092.33 h20
  text "LSD_FT2" at 4790.59,5043.95 h20
  text "HSD_FLT" at 4935.59,5043.95 h20
  text "STRAP2" at 3404,3969 h20
  text "C2UR_RX" at 4893.53,3392.8 h20
  text "C2UR_TX" at 5043.53,3392.8 h20
  text "GND" at 4719,3319 h20
  text "ADC4_0" at 4659,3287.33 h20
  text "ADC4_1" at 4809,3287.33 h20
  text "ADC3_0" at 4659,3262.33 h20
  text "ADC3_1" at 4809,3262.33 h20
  text "LS_OUTC" at 3579,3242.33 h20
  text "ADC4_2" at 3754,3242.33 h20
  text "ADC_C0" at 4659,3232.33 h20
  text "ADC_C1" at 4809,3232.33 h20
  text "ADC1_2" at 4659,3202.27 h20
  text "ADC1_3" at 4809,3202.33 h20
  text "ADC0_2" at 4659,3172.27 h20
  text "ADC0_3" at 4809,3172.27 h20
  text "HC_CS" at 3579,3137.33 h20
  text "ADC3_2" at 3754,3137.33 h20
  text "ADC_A0" at 4659,3107.27 h20
  text "ADC_A1" at 4809,3107.27 h20
  text "ADC2_2" at 3754,3037.33 h20
  text "IPROPI4" at 3579,3034 h20
  text "ADC2_0" at 3751.91,2950.12 h20
  text "IPROPI3" at 3576.91,2946.79 h20
  text "ADC1_0" at 3751.91,2850.12 h20
  text "IPROPI2" at 3576.91,2846.79 h20
  text "ADC0_0" at 3751.91,2750.12 h20
  text "IPROPI1" at 3576.91,2746.79 h20
  text "ＴＭＳ" at 5304,1884 h20
  text "ＴＲＳＴ" at 5399,1884 h20
  text "ＴＤＩ" at 5304,1849 h20
  text "ＧＮＤ" at 5399,1849 h20
  text "ＶＤＤＩＯ" at 5303.65,1807.06 h20
  text "ＴＤＯ" at 5303.65,1772.06 h20
  text "ＧＮＤ" at 5398.65,1772.06 h20
  text "ＴＣＫ" at 5304,1739 h20
  text "ＧＮＤ" at 5399,1739 h20
  text "ＴＣＫ" at 5304,1699 h20
  text "ＧＮＤ" at 5399,1699 h20
  text "ＥＭＵ０" at 5301.67,1661.72 h20
  text "ＥＭＵ１" at 5396.67,1661.72 h20
  text ".Layer_Name" at 577,-858.49 h60
Top Paste:
  text ".Layer_Name" at 577,-858.49 h60
Bottom Paste:
  text ".Layer_Name" at 577,-858.49 h60
Top Solder:
  text ".Layer_Name" at 577,-858.49 h60
  text ".Layer_Name" at 577,-858.49 h60
Bottom Solder:
  text ".Layer_Name" at 577,-858.49 h60
Drill Guide:
  text ".Layer_Name" at 577,-858.49 h60
Mechanical 1:
  lines w10: 0,0 5530,0 5530,6695 0,6695 0,0
  text ".Layer_Name" at 577,-858.49 h60
Top 3D Body:
  rectangle: 0,-275 125,-150
  rectangle: 125,-400 500,-275
  lines w7: 0,-275 1000,-275 ; 125,-400 125,-150 ; 250,-400 250,-150 ; 500,-400 500,-150 ; 750,-400 750,-150 ; 0,-400 1000,-400 1000,-150 0,-150 0,-400
  text ".Layer_Name" at 577,-858.49 h60
Mechanical 3:
  text ".Layer_Name" at 577,-858.49 h60
Top Courtyard:
  text ".Layer_Name" at 577,-858.49 h60
Mechanical 5:
  lines w10: -292,-930.17 6308,-930.17 ; -292,-726.83 6310,-726.83 ; -292,-523.5 -292,-1133.5 3713,-1133.5 6310,-1133.5 6310,-523.5 -291.5,-523.5 -291.5,-1133.5 1284,-1133.5 ; 2173,-1133.5 2173,-523.5 ; 3440,-726.83 3440,-523.5 ; 4280,-726.83 4280,-523.5 ; 4902,-1140 4902,-937.17
  text "COMPONENTS MARKED 'DNP' SHOULD NOT BE POPULATED." at 1153.5,-318.5 h60
  text "ASSEMBLY VARIANT:" at 1153,-434 h60
  text ".VariantName" at 2189,-434 h60
  text "PCB VIEWED FROM TOP SIDE" at -228.5,-655.67 h60
  text "BOARD #:" at 2248,-655.67 h60
  text ".PRJ_Number" at 2793.5,-655.67 h60
  text "REV:" at 3638,-655.67 h60
  text ".PCB_Rev" at 3929.5,-655.67 h60
  text "SVN REV:" at 4476,-655.67 h60
  text ".VersionControl_RevNumber" at 4982,-655.67 h60
  text "TID #:" at 2248,-859 h60
  text ".TID" at 2793.5,-859 h60
  text "PLOT NAME =" at -228.5,-1064.34 h60
  text ".plot_File_Name" at 577,-1064.34 h60
  text "GENERATED    :" at 2250,-1064.34 h60
  text ".Print_Date" at 3119.5,-1064.34 h60
  text ".Print_Time" at 3848.5,-1064.34 h60
  text "TEXAS INSTRUMENTS" at 5113,-1064.34 h60
Top Assembly:
  lines w10: -292.5,-727.33 6309.5,-727.33 ; -290.5,-930.67 6309.5,-930.67 ; 1115.5,-1140.5 1115.5,-937.67 ; 1737.5,-727.33 1737.5,-524 ; 2577.5,-727.33 2577.5,-524 ; 3844.5,-1134 3844.5,-524 ; 4733.5,-1134 6309,-1134 6309,-524 -292.5,-524 -292.5,-1134 2304.5,-1134 6309.5,-1134 6309.5,-524
  text "COMPONENTS MARKED 'DNP' SHOULD NOT BE POPULATED." at 6102,-318 h60
  text ".VariantName" at 5058,-434 h60
  text "ASSEMBLY VARIANT:" at 6097,-434 h60
  text ".VersionControl_RevNumber" at 1035.5,-656.17 h60
  text "SVN REV:" at 1541.5,-656.17 h60
  text ".PCB_Rev" at 2088,-656.17 h60
  text "REV:" at 2379.5,-656.17 h60
  text ".PRJ_Number" at 3224,-656.17 h60
  text "BOARD #:" at 3769.5,-656.17 h60
  text "PCB VIEWED FROM BOTTOM SIDE" at 6246,-656.17 h60
  text ".TID" at 3224,-859.5 h60
  text "TID #:" at 3769.5,-859.5 h60
  text "TEXAS INSTRUMENTS" at 904.5,-1064.84 h60
  text ".Print_Time" at 2169,-1064.84 h60
  text ".Print_Date" at 2898,-1064.84 h60
  text "GENERATED    :" at 3767.5,-1064.84 h60
  text ".plot_File_Name" at 5440.5,-1064.84 h60
  text "PLOT NAME =" at 6246,-1064.84 h60
Mechanical 9:
  lines w10: -491.5,1041.5 -291.5,1041.5 ; -491.5,3416.5 -291.5,3416.5 ; -491.5,5791.5 -291.5,5791.5 ; 2008.5,-1333.5 2008.5,-1133.5 ; 2008.5,7966.5 2008.5,8166.5 ; 4508.5,-1333.5 4508.5,-1133.5 ; 4508.5,7966.5 4508.5,8166.5 ; 6321,-1133.5 6321,-523.5 11303.5,-523.5 ; 7008.5,-1333.5 7008.5,-1133.5 ; 7008.5,7966.5 7008.5,8166.5 ; 9508.5,-1333.5 9508.5,-1133.5 ; 11303.5,-1133.5 11303.5,-523.5 ; 11303.5,-823.5 14303.5,-823.5 ; 11303.5,-223.5 14303.5,-223.5 ; 11303.5,76.5 11303.5,-523.5 ; 12008.5,-1333.5 12008.5,-1133.5 ; 12808.5,-1123.5 12808.5,-523.5 ; 14303.5,-523.5 11303.5,-523.5 ; 14308.5,66.5 14308.5,-1133.5 ; 14308.5,-1133.5 14308.5,7966.5 -291.5,7966.5 -291.5,-1133.5 14308.5,-1133.5 ; -491.5,-1333.5 -491.5,8166.5 14508.5,8166.5 14508.5,-1333.5 -491.5,-1333.5
  text "1" at 739.84,8036.5 h70
  text "2" at 3235.5,8036.5 h70
  text "3" at 5724.84,8036.5 h70
  text "4" at 8231.51,8036.5 h70
  text "A" at -416.5,6893.5 h70
  text "B" at -416.5,4513.5 h70
  text "C" at -416.5,2138.5 h70
  text "DESIGNED FOR:" at 11343.5,-23.5 h45
  text ".PRJ_Customer" at 11393.5,-163.5 h70
  text "D" at -416.5,-231.5 h70
  text "D" at 14383.5,-231.5 h70
  text "FILE NAME:" at 11343.5,-323.5 h45
  text ".PCB_File_Name_No_Path" at 11393.5,-443.5 h70
  text "Texas Instruments (TI) and/or its licensors do not warrant the accuracy or completeness of this specification" at 6374,-605.34 h45
  text "ENGINEER:" at 11343.5,-613.5 h45
  text "LAYOUT BY:" at 12848.5,-613.5 h45
  text "or any information contained therein. TI and/or its licensors do not warrant that this design will meet" at 6329.01,-718 h45
  text ".PRJ_Engineer" at 11393.5,-768.49 h70
  text ".PCB_Layout" at 12899,-768.49 h70
  text "the specifications, will be suitable for your application or fit for any particular purpose, or will operate in" at 6329.01,-830.67 h45
  text ".Layer_Name" at 577,-858.49 h60
  text "ALTIUM DESIGNER VERSION:" at 12848.5,-923.5 h45
  text "an implementation. TI and/or its licensors do not warrant that the design is production worthy. You should" at 6329.01,-943.33 h45
  text "completely validate and test your design implementation to confirm the system functionality for your application." at 6374,-1056 h45
  text ".print_Scale" at 11393.5,-1056.83 h70
  text ".Application_BuildNumber" at 12899,-1056.83 h70
  text "1" at 739.84,-1263.5 h70
  text "2" at 3235.5,-1263.5 h70
  text "3" at 5724.84,-1263.5 h70
  text "5" at 10730.5,-1263.5 h70
  text "6" at 13235.5,-1263.5 h70
Mechanical 10:
  text ".Layer_Name" at 577,-858.49 h60
Mechanical 11:
  lines w10: -292,-930.17 6308,-930.17 ; -292,-726.83 6310,-726.83 ; -292,-523.5 -292,-1133.5 3713,-1133.5 6310,-1133.5 6310,-523.5 -291.5,-523.5 -291.5,-1133.5 1284,-1133.5 ; 2173,-1133.5 2173,-523.5 ; 3440,-726.83 3440,-523.5 ; 4280,-726.83 4280,-523.5 ; 4902,-1140 4902,-937.17
  text "ALL ARTWORK VIEWED FROM TOP SIDE" at -228.5,-655.67 h60
  text "BOARD #:" at 2248,-655.67 h60
  text ".PRJ_Number" at 2793.5,-655.67 h60
  text "REV:" at 3638,-655.67 h60
  text ".PCB_Rev" at 3929.5,-655.67 h60
  text "SVN REV:" at 4476,-655.67 h60
  text ".VersionControl_RevNumber" at 4982,-655.67 h60
  text "LAYER NAME =" at -228.5,-858.49 h60
  text "TID #:" at 2248,-859 h60
  text ".TID" at 2793.5,-859 h60
  text "PLOT NAME =" at -228.5,-1064.34 h60
  text ".plot_File_Name" at 577,-1064.34 h60
  text "GENERATED    :" at 2250,-1064.34 h60
  text ".Print_Date" at 3119.5,-1064.34 h60
  text ".Print_Time" at 3848.5,-1064.34 h60
  text "TEXAS INSTRUMENTS" at 5113,-1064.34 h60
Mechanical 12:
  text ".Layer_Name" at 577,-858.49 h60
Mechanical 13:
  text ".Layer_Name" at 577,-858.49 h60
Mechanical 14:
  text ".Layer_Name" at 577,-858.49 h60
Mechanical 15:
  text ".Layer_Name" at 577,-858.49 h60
Top Component Center:
  text ".Layer_Name" at 577,-858.49 h60
Drill Drawing:
  region: 480,5085 550,5085 550,4805 545,4800 480,4800
  text ".Layer_Name" at 577,-858.49 h60
Mechanical 17:
  text ".Layer_Name" at 577,-858.49 h60
Mechanical 18:
  text ".Layer_Name" at 577,-858.49 h60
Mechanical 19:
  text ".Layer_Name" at 577,-858.49 h60

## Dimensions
0,-400 to 1000,-400 on Top 3D Body
5525,6695 to 5540,0 on Mechanical 1
0,6695 to 5520,6715 on Mechanical 1
0,0 to 0,0 on Top 3D Body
